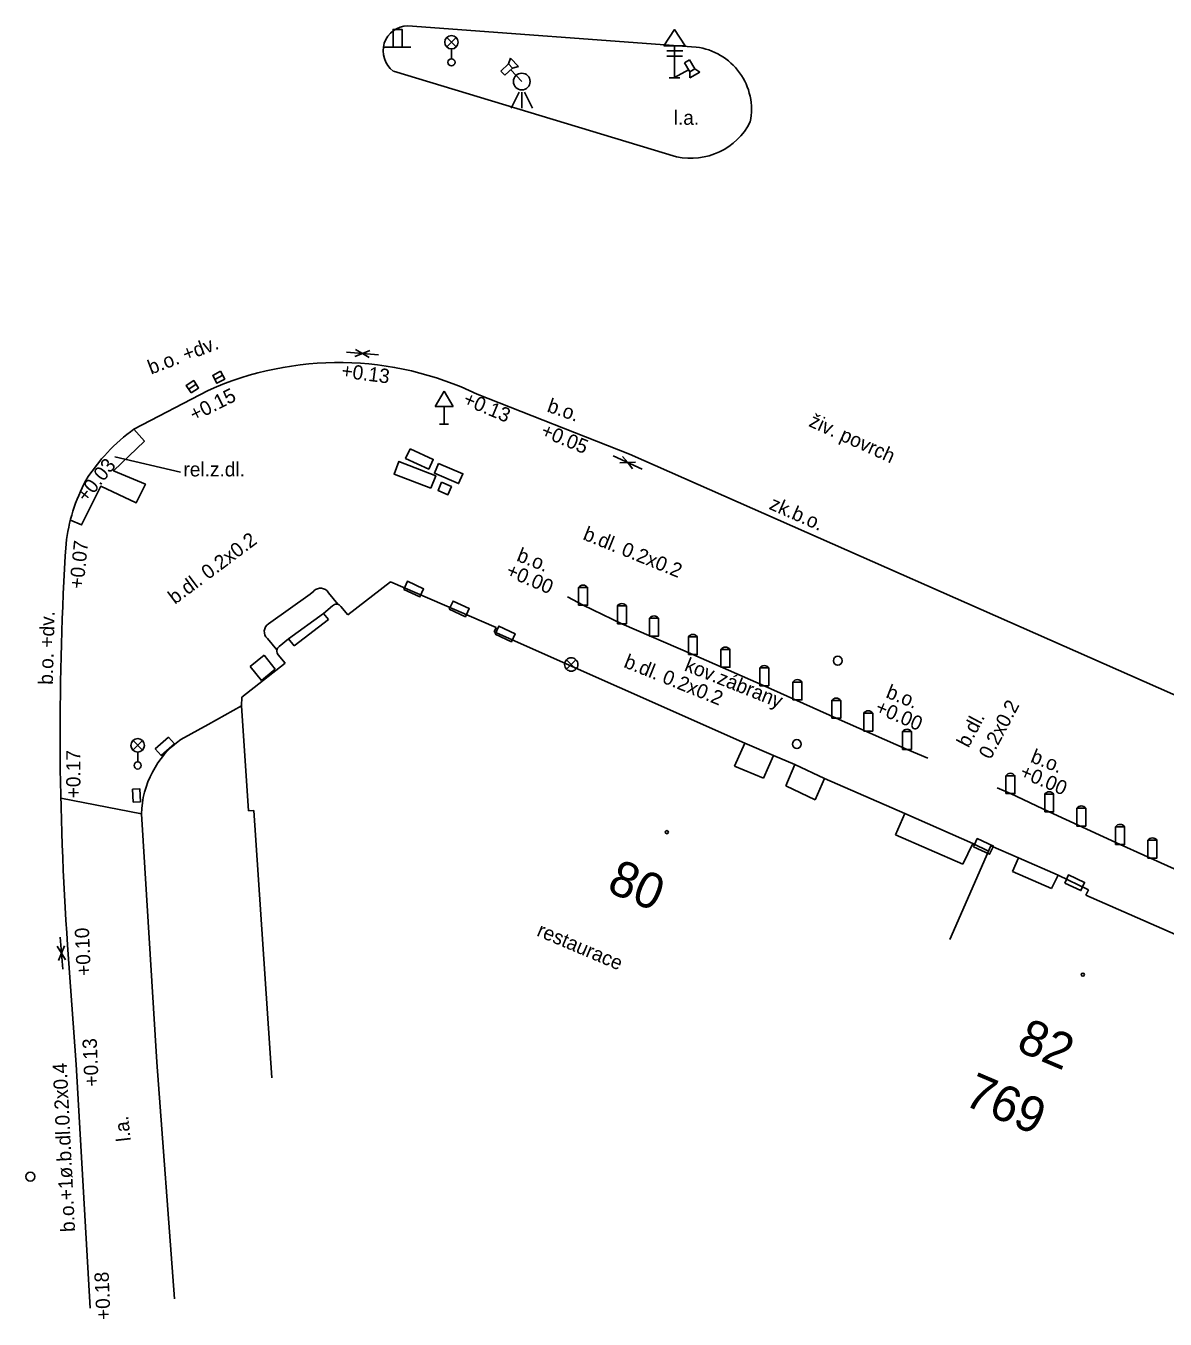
# Model space of a CAD drawing. Extents: x -596069 to -595934, y -1161686 to -1161593.
# Drawn here: x -596034.6 to -596002.69, y -1161675.28 to -1161639.03 of the extents above; entities that cross this region are included whole.
import ezdxf

# ---------------------------------------------------------------- set-up
doc = ezdxf.new("R2010")
doc.units = 0
for name, color, linetype in [('Vrstva 10', 7, 'Continuous'), ('Vrstva 15', 7, 'Continuous'), ('Vrstva 19', 7, 'Continuous'), ('Vrstva 2', 7, 'Continuous'), ('Vrstva 23', 7, 'Continuous'), ('Vrstva 25', 7, 'Continuous'), ('Vrstva 26', 7, 'Continuous'), ('Vrstva 29', 7, 'Continuous'), ('Vrstva 34', 7, 'Continuous'), ('Vrstva 4', 7, 'Continuous'), ('Vrstva 43', 7, 'Continuous'), ('Vrstva 44', 7, 'Continuous'), ('Vrstva 49', 7, 'Continuous'), ('Vrstva 5', 7, 'Continuous'), ('Vrstva 50', 7, 'Continuous'), ('Vrstva 7', 7, 'Continuous')]:
    doc.layers.add(name, color=color, linetype=linetype)

msp = doc.modelspace()

# ---------------------------------------------------------------- linework, layer by layer
at = {"layer": 'Vrstva 10'}
for p, q in [((-596029.496, -1161658.607), (-596030.263, -1161659.03)), ((-596031.366, -1161661.115), (-596030.933, -1161668.069)), ((-596030.933, -1161668.069), (-596030.435, -1161674.71))]:
    msp.add_line(p, q, dxfattribs=at)
msp.add_arc((-596028.708, -1161661.187), 2.659, 125.7852, 178.4556, dxfattribs=at)
at = {"layer": 'Vrstva 15'}
for centre in [(-596016.645, -1161661.626), (-596004.99, -1161665.62)]:
    msp.add_circle(centre, 0.0438, dxfattribs=at)
at = {"layer": 'Vrstva 19'}
for p, q in [((-596022.886, -1161649.263), (-596023.136, -1161649.696)), ((-596022.886, -1161649.263), (-596022.636, -1161649.696)), ((-596023.136, -1161649.696), (-596022.636, -1161649.696)), ((-596022.886, -1161650.196), (-596022.886, -1161649.696)), ((-596023.011, -1161650.196), (-596022.761, -1161650.196))]:
    msp.add_line(p, q, dxfattribs=at)
for points in [[(-596024.315, -1161639.63), (-596024.315, -1161639.13), (-596024.065, -1161639.13), (-596024.065, -1161639.63)], [(-596024.565, -1161639.63), (-596023.815, -1161639.63)]]:
    msp.add_lwpolyline(points, dxfattribs=at)
at = {"layer": 'Vrstva 2'}
for p, q in [((-596019.455, -1161656.795), (-596019.323, -1161656.927)), ((-596019.191, -1161656.795), (-596019.323, -1161656.927)), ((-596019.455, -1161657.059), (-596019.323, -1161656.927)), ((-596019.323, -1161656.927), (-596019.455, -1161657.059)), ((-596019.191, -1161657.059), (-596019.323, -1161656.927)), ((-596019.323, -1161656.927), (-596019.191, -1161657.059)), ((-596019.323, -1161656.927), (-596019.191, -1161657.059))]:
    msp.add_line(p, q, dxfattribs=at)
for start, end in [(134.9922, 225.0078), (44.9922, 135.0078), (314.9921, 45.0078), (224.9922, 315.0078)]:
    msp.add_arc((-596019.323, -1161656.927), 0.187, start, end, dxfattribs=at)
at = {"layer": 'Vrstva 23'}
for p, q in [((-596027.928, -1161656.669), (-596028.318, -1161656.981)), ((-596027.615, -1161657.059), (-596027.928, -1161656.669)), ((-596028.318, -1161656.981), (-596028.005, -1161657.372)), ((-596028.005, -1161657.372), (-596027.615, -1161657.059))]:
    msp.add_line(p, q, dxfattribs=at)
msp.add_circle((-596034.478, -1161671.282), 0.125, dxfattribs=at)
at = {"layer": 'Vrstva 25'}
for p, q in [((-596029.088, -1161648.819), (-596029.308, -1161648.937)), ((-596030.042, -1161649.213), (-596029.834, -1161649.075))]:
    msp.add_line(p, q, dxfattribs=at)
for points in [[(-596029.146, -1161648.709), (-596029.367, -1161648.826), (-596029.25, -1161649.047), (-596029.029, -1161648.93)], [(-596029.974, -1161649.317), (-596029.765, -1161649.18), (-596029.902, -1161648.971), (-596030.111, -1161649.108)]]:
    msp.add_lwpolyline(points, close=True, dxfattribs=at)
at = {"layer": 'Vrstva 26'}
for centre in [(-596011.855, -1161656.822), (-596013.003, -1161659.159)]:
    msp.add_circle(centre, 0.125, dxfattribs=at)
at = {"layer": 'Vrstva 29'}
for p, q in [((-596022.812, -1161639.619), (-596022.548, -1161639.355)), ((-596022.544, -1161639.618), (-596022.808, -1161639.353)), ((-596022.68, -1161639.95), (-596022.68, -1161639.675)), ((-596031.602, -1161659.326), (-596031.338, -1161659.062)), ((-596031.334, -1161659.325), (-596031.598, -1161659.06)), ((-596031.47, -1161659.657), (-596031.47, -1161659.382))]:
    msp.add_line(p, q, dxfattribs=at)
for points in [[(-596023.84, -1161650.88), (-596023.19, -1161651.18), (-596023.316, -1161651.452), (-596023.966, -1161651.152)], [(-596023.258, -1161651.99), (-596024.288, -1161651.592), (-596024.151, -1161651.238), (-596023.121, -1161651.636)], [(-596023.04, -1161651.29), (-596022.36, -1161651.58), (-596022.478, -1161651.856), (-596023.158, -1161651.566)], [(-596022.956, -1161651.822), (-596022.681, -1161651.94), (-596022.779, -1161652.17), (-596023.054, -1161652.052)], [(-596024.018, -1161654.824), (-596023.565, -1161655.035), (-596023.46, -1161654.808), (-596023.913, -1161654.597)], [(-596022.74, -1161655.377), (-596022.287, -1161655.588), (-596022.182, -1161655.361), (-596022.635, -1161655.15)], [(-596021.454, -1161656.08), (-596021.001, -1161656.291), (-596020.896, -1161656.064), (-596021.349, -1161655.853)], [(-596030.608, -1161658.961), (-596030.979, -1161659.295), (-596030.812, -1161659.481), (-596030.441, -1161659.147)], [(-596031.613, -1161660.422), (-596031.593, -1161660.786), (-596031.393, -1161660.775), (-596031.413, -1161660.411)], [(-596005.499, -1161663.053), (-596005.046, -1161663.264), (-596004.941, -1161663.037), (-596005.394, -1161662.826)]]:
    msp.add_lwpolyline(points, close=True, dxfattribs=at)
for centre, radius in [((-596022.68, -1161639.488), 0.188), ((-596022.68, -1161640.05), 0.1), ((-596031.47, -1161659.194), 0.188), ((-596031.47, -1161659.757), 0.1)]:
    msp.add_circle(centre, radius, dxfattribs=at)
at = {"layer": 'Vrstva 34'}
msp.add_lwpolyline([(-596008.055, -1161662.035), (-596007.602, -1161662.246), (-596007.497, -1161662.019), (-596007.95, -1161661.808)], close=True, dxfattribs=at)
at = {"layer": 'Vrstva 4'}
for p, q in [((-596026.015, -1161655.283), (-596026.268, -1161655.501)), ((-596026.123, -1161655.669), (-596026.268, -1161655.501)), ((-596021.486, -1161656.016), (-596014.463, -1161659.135)), ((-596027.504, -1161656.421), (-596027.242, -1161656.212)), ((-596027.086, -1161656.408), (-596027.242, -1161656.212)), ((-596028.55, -1161657.845), (-596027.338, -1161656.895)), ((-596028.563, -1161658.091), (-596028.55, -1161657.845)), ((-596014.463, -1161659.135), (-596014.747, -1161659.775)), ((-596013.658, -1161659.475), (-596013.935, -1161660.118)), ((-596013.055, -1161659.735), (-596013.312, -1161660.332)), ((-596009.982, -1161661.104), (-596010.242, -1161661.7)), ((-596008.07, -1161661.943), (-596008.353, -1161662.528)), ((-596007.632, -1161662.155), (-596008.07, -1161661.943)), ((-596000.293, -1161665.422), (-596004.908, -1161663.397))]:
    msp.add_line(p, q, dxfattribs=at)
for points in [[(-596024.39, -1161654.61), (-596025.579, -1161655.534)], [(-596024.39, -1161654.61), (-596021.43, -1161655.887)], [(-596026.642, -1161654.953), (-596027.804, -1161655.79)], [(-596026.642, -1161654.953), (-596026.535, -1161654.868)], [(-596026.129, -1161654.915), (-596025.864, -1161655.238)], [(-596025.579, -1161655.534), (-596025.78, -1161655.3)], [(-596027.242, -1161656.212), (-596026.268, -1161655.501)], [(-596021.43, -1161655.887), (-596021.486, -1161656.016)], [(-596027.837, -1161656.197), (-596027.572, -1161656.52)], [(-596027.338, -1161656.895), (-596027.531, -1161656.653)], [(-596028.563, -1161658.091), (-596028.362, -1161661.031)], [(-596014.463, -1161659.135), (-596013.658, -1161659.475)], [(-596013.055, -1161659.735), (-596013.658, -1161659.475)], [(-596013.055, -1161659.735), (-596012.227, -1161660.125)], [(-596012.227, -1161660.125), (-596012.487, -1161660.721)], [(-596009.982, -1161661.104), (-596012.227, -1161660.125)], [(-596028.362, -1161661.031), (-596028.212, -1161661.021)], [(-596028.212, -1161661.021), (-596027.712, -1161668.515)], [(-596009.982, -1161661.104), (-596008.07, -1161661.943)], [(-596007.568, -1161662.008), (-596008.714, -1161664.64)], [(-596006.794, -1161662.345), (-596007.568, -1161662.008)], [(-596006.794, -1161662.345), (-596006.962, -1161662.73)], [(-596006.794, -1161662.345), (-596005.686, -1161662.83)], [(-596005.686, -1161662.83), (-596005.87, -1161663.208)], [(-596004.834, -1161663.244), (-596005.686, -1161662.83)], [(-596004.834, -1161663.244), (-596004.908, -1161663.397)]]:
    msp.add_lwpolyline(points, dxfattribs=at)
for centre, radius, start, end in [((-596026.349, -1161655.043), 0.255, 30.0893, 136.648), ((-596025.904, -1161655.386), 0.151, 35.1999, 136.5609), ((-596027.669, -1161656.006), 0.255, 122.0852, 228.6439), ((-596027.422, -1161656.548), 0.151, 122.6813, 224.0423)]:
    msp.add_arc(centre, radius, start, end, dxfattribs=at)
at = {"layer": 'Vrstva 44'}
for p, q in [((-596016.649, -1161639.732), (-596016.201, -1161639.732)), ((-596016.429, -1161639.582), (-596016.429, -1161640.482)), ((-596021.079, -1161640.095), (-596021.293, -1161640.294)), ((-596021.022, -1161639.931), (-596021.079, -1161640.095)), ((-596020.968, -1161640.215), (-596021.079, -1161640.095)), ((-596021.079, -1161640.095), (-596020.968, -1161640.215)), ((-596020.799, -1161640.169), (-596021.022, -1161639.931)), ((-596016.649, -1161639.882), (-596016.206, -1161639.882)), ((-596016.008, -1161639.981), (-596016.15, -1161640.062)), ((-596016.15, -1161640.062), (-596016.005, -1161640.316)), ((-596015.864, -1161640.235), (-596016.008, -1161639.981)), ((-596021.293, -1161640.294), (-596021.182, -1161640.414)), ((-596021.182, -1161640.414), (-596020.968, -1161640.215)), ((-596021.017, -1161640.26), (-596020.71, -1161640.59)), ((-596020.968, -1161640.215), (-596020.799, -1161640.169)), ((-596016.579, -1161640.482), (-596016.279, -1161640.482)), ((-596016.038, -1161640.257), (-596016.43, -1161640.48)), ((-596016.005, -1161640.316), (-596015.864, -1161640.235)), ((-596015.864, -1161640.235), (-596016.005, -1161640.316)), ((-596016.005, -1161640.316), (-596016, -1161640.49)), ((-596016, -1161640.49), (-596015.717, -1161640.328)), ((-596015.717, -1161640.328), (-596015.864, -1161640.235)), ((-596020.784, -1161640.883), (-596021.01, -1161641.335)), ((-596020.71, -1161640.885), (-596020.71, -1161641.335)), ((-596020.635, -1161640.883), (-596020.41, -1161641.335))]:
    msp.add_line(p, q, dxfattribs=at)
for points in [[(-596016.729, -1161639.587), (-596016.429, -1161639.132), (-596016.129, -1161639.587)], [(-596019.117, -1161655.268), (-596018.867, -1161655.268), (-596018.867, -1161654.768), (-596019.117, -1161654.768)], [(-596018.03, -1161655.785), (-596017.78, -1161655.785), (-596017.78, -1161655.285), (-596018.03, -1161655.285)], [(-596017.128, -1161656.133), (-596016.878, -1161656.133), (-596016.878, -1161655.633), (-596017.128, -1161655.633)], [(-596016.041, -1161656.65), (-596015.791, -1161656.65), (-596015.791, -1161656.15), (-596016.041, -1161656.15)], [(-596015.128, -1161657.007), (-596014.878, -1161657.007), (-596014.878, -1161656.507), (-596015.128, -1161656.507)], [(-596014.041, -1161657.524), (-596013.791, -1161657.524), (-596013.791, -1161657.024), (-596014.041, -1161657.024)], [(-596013.111, -1161657.919), (-596012.861, -1161657.919), (-596012.861, -1161657.419), (-596013.111, -1161657.419)], [(-596012.024, -1161658.436), (-596011.774, -1161658.436), (-596011.774, -1161657.936), (-596012.024, -1161657.936)], [(-596011.128, -1161658.792), (-596010.878, -1161658.792), (-596010.878, -1161658.292), (-596011.128, -1161658.292)], [(-596010.041, -1161659.309), (-596009.791, -1161659.309), (-596009.791, -1161658.809), (-596010.041, -1161658.809)], [(-596007.145, -1161660.544), (-596006.895, -1161660.544), (-596006.895, -1161660.044), (-596007.145, -1161660.044)], [(-596006.058, -1161661.061), (-596005.808, -1161661.061), (-596005.808, -1161660.561), (-596006.058, -1161660.561)], [(-596005.158, -1161661.457), (-596004.908, -1161661.457), (-596004.908, -1161660.957), (-596005.158, -1161660.957)], [(-596004.071, -1161661.974), (-596003.821, -1161661.974), (-596003.821, -1161661.474), (-596004.071, -1161661.474)], [(-596003.166, -1161662.353), (-596002.916, -1161662.353), (-596002.916, -1161661.853), (-596003.166, -1161661.853)]]:
    msp.add_lwpolyline(points, close=True, dxfattribs=at)
msp.add_circle((-596020.71, -1161640.59), 0.234, dxfattribs=at)
for centre in [(-596018.992, -1161654.853), (-596017.905, -1161655.37), (-596017.003, -1161655.718), (-596015.916, -1161656.235), (-596015.003, -1161656.592), (-596013.916, -1161657.109), (-596012.986, -1161657.504), (-596011.899, -1161658.021), (-596011.003, -1161658.377), (-596009.916, -1161658.894), (-596007.02, -1161660.129), (-596005.933, -1161660.646), (-596005.033, -1161661.042), (-596003.946, -1161661.559), (-596003.041, -1161661.938)]:
    msp.add_arc(centre, 0.151, 34.3319, 145.6681, dxfattribs=at)
at = {"layer": 'Vrstva 49'}
for p, q in [((-596025.174, -1161648.21), (-596025.365, -1161648.095)), ((-596024.725, -1161648.25), (-596025.623, -1161648.17)), ((-596025.174, -1161648.21), (-596025.383, -1161648.291)), ((-596025.174, -1161648.21), (-596024.967, -1161648.127)), ((-596025.174, -1161648.21), (-596024.986, -1161648.327)), ((-596032.112, -1161651.107), (-596030.267, -1161651.539)), ((-596017.332, -1161651.457), (-596018.152, -1161651.083)), ((-596017.742, -1161651.27), (-596017.966, -1161651.277)), ((-596017.742, -1161651.27), (-596017.884, -1161651.098)), ((-596017.742, -1161651.27), (-596017.519, -1161651.261)), ((-596017.742, -1161651.27), (-596017.604, -1161651.443)), ((-596033.643, -1161664.567), (-596033.569, -1161665.465)), ((-596033.606, -1161665.016), (-596033.722, -1161664.826)), ((-596033.606, -1161665.016), (-596033.687, -1161665.224)), ((-596033.606, -1161665.016), (-596033.523, -1161664.811)), ((-596033.606, -1161665.016), (-596033.491, -1161665.209))]:
    msp.add_line(p, q, dxfattribs=at)
at = {"layer": 'Vrstva 5'}
for p, q in [((-596026.123, -1161655.669), (-596027.086, -1161656.408)), ((-596029.496, -1161658.607), (-596028.563, -1161658.091)), ((-596013.935, -1161660.118), (-596014.747, -1161659.775)), ((-596012.487, -1161660.721), (-596013.312, -1161660.332)), ((-596008.353, -1161662.528), (-596010.242, -1161661.7)), ((-596006.962, -1161662.73), (-596005.873, -1161663.207))]:
    msp.add_line(p, q, dxfattribs=at)
at = {"layer": 'Vrstva 7'}
for p, q in [((-596023.9, -1161639.029), (-596015.82, -1161639.622)), ((-596024.308, -1161640.295), (-596016.373, -1161642.7)), ((-596009.916, -1161659.309), (-596009.329, -1161659.557)), ((-596007.02, -1161660.544), (-596007.387, -1161660.383)), ((-596007.02, -1161660.544), (-596005.933, -1161661.061)), ((-596005.933, -1161661.061), (-596003.946, -1161661.974)), ((-596003.946, -1161661.974), (-596001.954, -1161662.87))]:
    msp.add_line(p, q, dxfattribs=at)
for points in [[(-596029.493, -1161649.245), (-596031.576, -1161650.332)], [(-595992.773, -1161662.939), (-595992.538, -1161662.463), (-595992.446, -1161662.231), (-596001.752, -1161658.08), (-596017.691, -1161651.031), (-596021.958, -1161649.351)], [(-596031.576, -1161650.332), (-596031.28, -1161650.673), (-596032.144, -1161651.5), (-596031.254, -1161651.877), (-596031.509, -1161652.396), (-596032.505, -1161651.931), (-596033.043, -1161653.018), (-596033.357, -1161652.887)], [(-596019.433, -1161655.034), (-596018.992, -1161655.268), (-596017.905, -1161655.785), (-596015.916, -1161656.65), (-596013.916, -1161657.524), (-596011.899, -1161658.436), (-596009.916, -1161659.309)], [(-596033.624, -1161660.675), (-596031.366, -1161661.115)], [(-596033.434, -1161664.796), (-596033.193, -1161668.136), (-596032.803, -1161674.972)]]:
    msp.add_lwpolyline(points, dxfattribs=at)
for centre, radius, start, end in [((-596023.893, -1161639.73), 0.701, 90.6111, 233.6633), ((-596016.039, -1161641.375), 1.766, 348.7278, 82.8677), ((-596015.979, -1161640.862), 1.88, 257.9096, 332.8447), ((-596025.84, -1161657.408), 8.943, 64.2771, 114.111), ((-596028.611, -1161654.457), 5.08, 125.7104, 148.026), ((-596028.582, -1161654.105), 4.928, 151.6799, 173.4646), ((-595949.041, -1161658.84), 84.603, 176.41081, 184.03682)]:
    msp.add_arc(centre, radius, start, end, dxfattribs=at)

# ---------------------------------------------------------------- texts
at = {"layer": 'Vrstva 43'}
for s, p in [('80', (-596018.363, -1161663.276)), ('82', (-596006.891, -1161667.732)), ('769', (-596008.366, -1161669.256))]:
    msp.add_text(s, height=1, rotation=337, dxfattribs=at).set_placement(p)
at = {"layer": 'Vrstva 49'}
for s, p in [('l.a.', (-596016.453, -1161641.802)), ('rel.z.dl.', (-596030.188, -1161651.657))]:
    msp.add_text(s, height=0.4, dxfattribs=at).set_placement(p)
for s, rotation, p in [('b.o. +dv.', 20.83, (-596031.097, -1161648.805)), ('b.o.', 340.6668, (-596020.026, -1161649.833)), ('živ. povrch', 335.6106, (-596012.695, -1161650.239)), ('zk.b.o.', 336.3515, (-596013.807, -1161652.561)), ('b.dl. 0.2x0.2', 338.0264, (-596019.023, -1161653.416)), ('b.dl. 0.2x0.2', 36.767, (-596030.428, -1161655.258)), ('b.o.', 338.3168, (-596020.879, -1161654.013)), ('b.o. +dv.', 88.5094, (-596033.849, -1161657.5)), ('b.dl. 0.2x0.2', 338.0264, (-596017.878, -1161656.994)), ('kov.zábrany', 338.3168, (-596016.179, -1161657.091)), ('b.o.', 338.3168, (-596010.534, -1161657.845)), ('0.2x0.2', 62.1022, (-596007.576, -1161659.612)), ('b.dl.', 62.1022, (-596008.195, -1161659.284)), ('b.o.', 338.3168, (-596006.482, -1161659.654)), ('restaurace', 337, (-596020.315, -1161664.52)), ('b.o.+1ø.b.dl.0.2x0.4', 92.8465, (-596033.224, -1161672.824)), ('l.a.', 96.454, (-596031.661, -1161670.275))]:
    msp.add_text(s, height=0.4, rotation=rotation, dxfattribs=at).set_placement(p)
at = {"layer": 'Vrstva 50'}
for s, rotation, p in [('+0.13', 352.738, (-596025.78, -1161648.882)), ('+0.15', 26.482, (-596029.89, -1161650.124)), ('+0.13', 337.2966, (-596022.382, -1161649.634)), ('+0.05', 337.599, (-596020.205, -1161650.52)), ('+0.03', 51.2266, (-596032.907, -1161652.408)), ('+0.07', 84.0317, (-596032.995, -1161654.82)), ('+0.00', 337.063, (-596021.183, -1161654.437)), ('+0.00', 337.063, (-596010.838, -1161658.269)), ('+0.17', 90, (-596033.074, -1161660.679)), ('+0.00', 337.063, (-596006.786, -1161660.078)), ('+0.10', 92.5228, (-596032.778, -1161665.647)), ('+0.13', 92.5228, (-596032.561, -1161668.748)), ('+0.18', 92.5228, (-596032.227, -1161675.292))]:
    msp.add_text(s, height=0.4, rotation=rotation, dxfattribs=at).set_placement(p)

doc.saveas('drawing.dxf')
